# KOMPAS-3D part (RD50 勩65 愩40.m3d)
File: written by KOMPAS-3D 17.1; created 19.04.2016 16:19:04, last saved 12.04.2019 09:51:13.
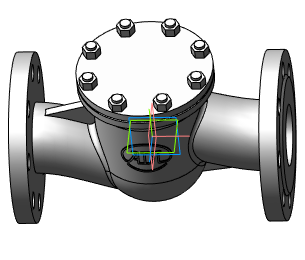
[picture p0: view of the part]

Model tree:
1. Операция без истории:2  (labels: Сталь 20  ГОСТ 1050-88)

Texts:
  RD50 Ду15 Ру40
  RD50 Ду20 Ру40
  RD50 Ду25 Ру40
  RD50 Ду32 Ру40
  RD50 Ду40 Ру40
  RD50 Ду50 Ру40
  RD50 Ду65 Ру40
  RD50 Ду80 Ру40
  RD50 Ду100 Ру40
  RD50 Ду125 Ру40
  RD50 Ду150 Ру40
  RD50 Ду200 Ру40
  RD50 Ду250 Ру40
  RD50 Ду300 Ру40
  RD50 Ду350 Ру40
  RD50 Ду400 Ру40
